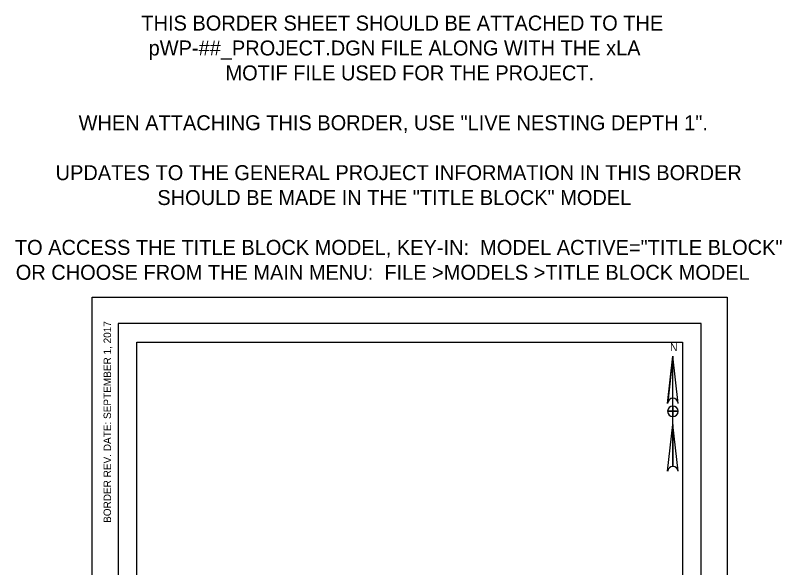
# Model space of a CAD drawing. Extents: x -1 to 9.2, y 0 to 14.8.
# Drawn here: x -1.03 to 9.23, y 7.38 to 14.77 of the extents above; entities that cross this region are included whole.
import ezdxf

# ---------------------------------------------------------------- set-up
doc = ezdxf.new("R2010")
doc.units = 0
for name, color, linetype in [('BORD-LINE', 7, 'Continuous'), ('NRTH-ARRO', 7, 'Continuous'), ('USER-CLIP', 7, 'Continuous'), ('USER-PAGE', 7, 'Continuous'), ('USER-TEXT', 7, 'Continuous')]:
    doc.layers.add(name, color=color, linetype=linetype)

msp = doc.modelspace()

# ---------------------------------------------------------------- linework, layer by layer
at = {"layer": 'BORD-LINE'}
msp.add_lwpolyline([(0.35, 0.861), (0.35, 0.35), (8.15, 0.35), (8.15, 10.65), (0.35, 10.65), (0.35, 0.861)], dxfattribs=at)
at = {"layer": 'NRTH-ARRO'}
for p, q in [((7.702, 9.58), (7.772, 10.213)), ((7.772, 8.738), (7.772, 10.213)), ((7.842, 9.58), (7.772, 10.213)), ((7.772, 9.475), (7.772, 9.546)), ((7.702, 9.475), (7.772, 9.475)), ((7.702, 9.475), (7.702, 9.475)), ((7.702, 9.475), (7.702, 9.475)), ((7.842, 9.475), (7.772, 9.475)), ((7.772, 9.475), (7.772, 9.405)), ((7.842, 9.475), (7.842, 9.475)), ((7.842, 9.475), (7.842, 9.475)), ((7.702, 8.676), (7.772, 9.299)), ((7.841, 8.676), (7.772, 9.299))]:
    msp.add_line(p, q, dxfattribs=at)
for points in [[(7.772, 9.65), (7.772, 9.65), (7.772, 10.213), (7.703, 9.596)], [(7.772, 9.546), (7.772, 9.475), (7.842, 9.475)], [(7.772, 9.405), (7.772, 9.475), (7.702, 9.475), (7.702, 9.475)], [(7.772, 9.405), (7.772, 9.405)], [(7.841, 8.676), (7.772, 9.299), (7.772, 8.738)]]:
    msp.add_lwpolyline(points, dxfattribs=at)
for centre, radius, start, end in [((7.772, 9.58), 0.0703, 90, 180), ((7.772, 9.58), 0.0703, 90.0905, 167.3484), ((7.772, 9.58), 0.0703, 0, 90), ((7.772, 9.475), 0.0703, 90, 180), ((7.772, 9.475), 0.0703, 0, 90), ((7.772, 9.475), 0.0703, 0.0012, 89.9988), ((7.772, 9.475), 0.0703, 180, 270), ((7.772, 9.475), 0.0703, 180, 270), ((7.772, 9.475), 0.0703, 270, 360), ((7.772, 8.668), 0.0698, 6.3439, 173.6561), ((7.772, 8.668), 0.0698, 6.3439, 90)]:
    msp.add_arc(centre, radius, start, end, dxfattribs=at)
at = {"layer": 'USER-CLIP'}
msp.add_lwpolyline([(0.6, 10.4), (7.9, 10.4), (7.9, 1.95), (0.6, 1.95)], close=True, dxfattribs=at)
at = {"layer": 'USER-PAGE'}
msp.add_lwpolyline([(0, 11), (8.5, 11), (8.5, 0), (0, 0)], close=True, dxfattribs=at)

# ---------------------------------------------------------------- texts
at = {"layer": 'NRTH-ARRO'}
msp.add_text('N', height=0.105, dxfattribs=at).set_placement((7.734, 10.283))
at = {"layer": 'USER-TEXT'}
for s, p in [('THIS BORDER SHEET SHOULD BE ATTACHED TO THE', (0.659, 14.566)), ('pWP-##_PROJECT.DGN FILE ALONG WITH THE xLA ', (0.756, 14.233)), ('MOTIF FILE USED FOR THE PROJECT.', (1.785, 13.9)), ('WHEN ATTACHING THIS BORDER, USE "LIVE NESTING DEPTH 1".', (-0.181, 13.233)), ('UPDATES TO THE GENERAL PROJECT INFORMATION IN THIS BORDER', (-0.489, 12.566)), ('SHOULD BE MADE IN THE "TITLE BLOCK" MODEL', (0.873, 12.233)), ('TO ACCESS THE TITLE BLOCK MODEL, KEY-IN:  MODEL ACTIVE="TITLE BLOCK"', (-1.034, 11.567)), ('OR CHOOSE FROM THE MAIN MENU:  FILE >MODELS >TITLE BLOCK MODEL', (-1.022, 11.233))]:
    msp.add_text(s, height=0.2, dxfattribs=at).set_placement(p)
msp.add_text('BORDER REV. DATE: SEPTEMBER 1, 2017', height=0.1, rotation=90, dxfattribs=at).set_placement((0.253, 7.983))

doc.saveas('drawing.dxf')
